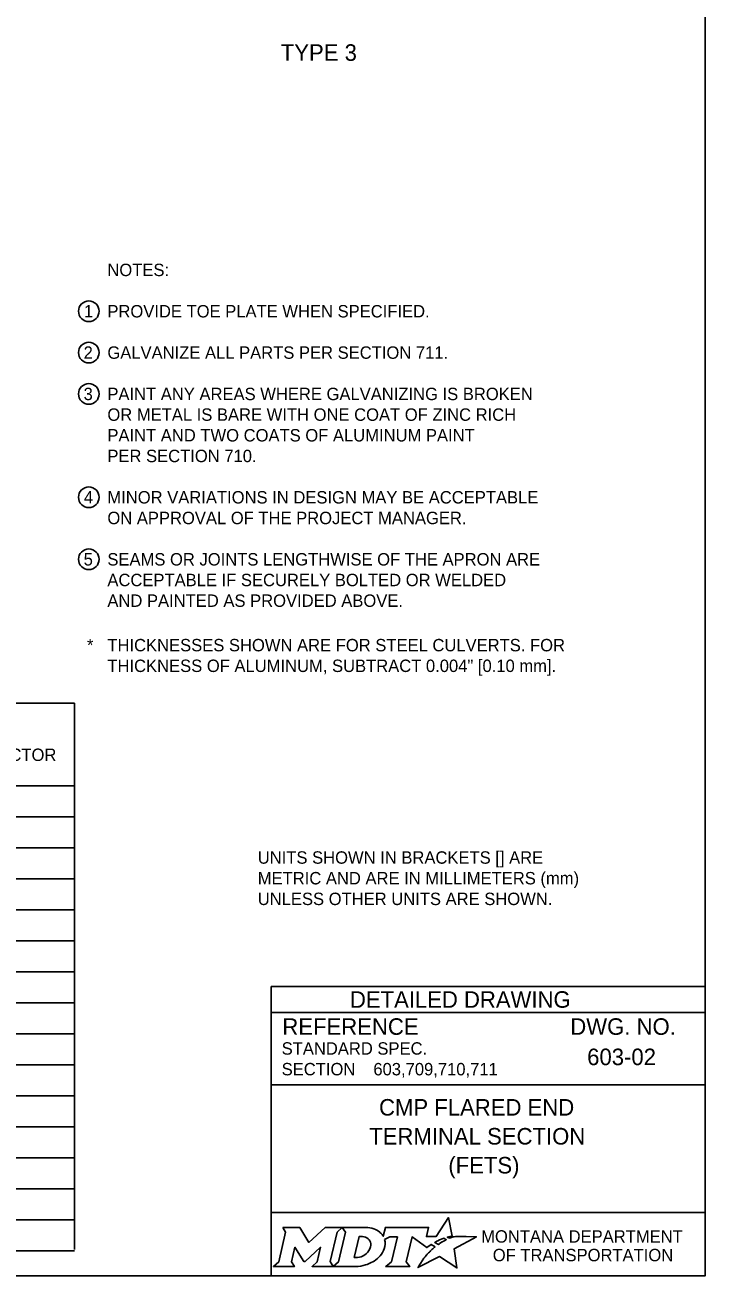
# Model space of a CAD drawing. Extents: x 49991.4 to 50021, y 49987.6 to 50011.4.
# Drawn here: x 50013.46 to 50016.75, y 49987.8 to 49993.85 of the extents above; entities that cross this region are included whole.
import ezdxf

# ---------------------------------------------------------------- set-up
doc = ezdxf.new("R2010")
doc.units = 0
for name, color, linetype in [('Default', 7, 'Continuous'), ('Level 1', 7, 'Continuous'), ('Level 2', 7, 'Continuous'), ('Level 5', 7, 'Continuous')]:
    doc.layers.add(name, color=color, linetype=linetype)

msp = doc.modelspace()

# ---------------------------------------------------------------- linework, layer by layer
at = {"layer": 'Default'}
for points in [[(50015.5126, 49987.9811), (50015.5023, 49987.9867), (50015.5139, 49987.9895), (50015.5255, 49987.9915), (50015.5081, 49988.0816), (50015.4486, 49987.9903), (50015.4013, 49987.9896), (50015.4116, 49988.0337), (50015.2024, 49988.0338), (50015.1923, 49987.9913), (50015.1865, 49987.9996)], [(50014.7056, 49988.0338), (50014.7197, 49988.0104), (50014.6862, 49987.8671), (50014.6605, 49987.8446), (50014.7621, 49987.8446), (50014.7486, 49987.8674), (50014.7648, 49987.9375), (50014.8085, 49987.8685), (50014.8138, 49987.8685), (50014.8889, 49987.938), (50014.8725, 49987.8669), (50014.8478, 49987.8449), (50014.9494, 49987.8449), (50014.9356, 49987.8682), (50014.9688, 49988.0106)], [(50014.9688, 49988.0106), (50014.9941, 49988.0338), (50014.9117, 49988.0338), (50014.8321, 49987.9608), (50014.7876, 49988.0335), (50014.7056, 49988.0338)], [(50015.1077, 49988.0338), (50014.9941, 49988.0338), (50015.0088, 49988.0109), (50014.9749, 49987.8671), (50014.9494, 49987.8449), (50015.06, 49987.8449)], [(50015.1317, 49987.9471), (50015.1305, 49987.939), (50015.1273, 49987.9297), (50015.1231, 49987.9215), (50015.1175, 49987.914), (50015.111, 49987.9071), (50015.1031, 49987.9008), (50015.0948, 49987.8961), (50015.0857, 49987.8922), (50015.0766, 49987.8899), (50015.0674, 49987.889), (50015.0515, 49987.889), (50015.0751, 49987.989), (50015.0911, 49987.989), (50015.0987, 49987.9884), (50015.1063, 49987.9865), (50015.1129, 49987.9835), (50015.119, 49987.9793), (50015.1238, 49987.9743), (50015.1275, 49987.9683), (50015.1302, 49987.9621), (50015.1318, 49987.9547), (50015.1318, 49987.9517), (50015.1317, 49987.9471)], [(50015.1991, 49987.9747), (50015.2237, 49987.9878), (50015.2606, 49987.9878), (50015.232, 49987.8673), (50015.2045, 49987.8446), (50015.3207, 49987.8446), (50015.3037, 49987.8675), (50015.3319, 49987.9877), (50015.4032, 49987.936), (50015.4243, 49987.9511), (50015.444, 49987.9402)], [(50015.3882, 49987.8843), (50015.3729, 49987.8599), (50015.3682, 49987.8524), (50015.3624, 49987.8438), (50015.3601, 49987.8395), (50015.4654, 49987.8926), (50015.5493, 49987.8375), (50015.5362, 49987.9302), (50015.6431, 49987.9886), (50015.5938, 49987.9894), (50015.5637, 49987.9898), (50015.5429, 49987.9901), (50015.5361, 49987.9886), (50015.5312, 49987.9874), (50015.5228, 49987.9851), (50015.5126, 49987.9811)], [(50015.4622, 49987.9535), (50015.4598, 49987.9518), (50015.4415, 49987.9614), (50015.4518, 49987.9671), (50015.4559, 49987.9693), (50015.4645, 49987.9733), (50015.4702, 49987.9759), (50015.4781, 49987.9789), (50015.4854, 49987.9816), (50015.4972, 49987.9742), (50015.4932, 49987.9721), (50015.4886, 49987.9696), (50015.4844, 49987.9674), (50015.4794, 49987.9645), (50015.4775, 49987.9634), (50015.4748, 49987.9618), (50015.4723, 49987.9604), (50015.47, 49987.9588), (50015.4674, 49987.957), (50015.4647, 49987.9552), (50015.4622, 49987.9535)], [(50015.1057, 49987.8522), (50015.1141, 49987.8548), (50015.1271, 49987.8602), (50015.1475, 49987.8712)], [(50015.4021, 49987.9004), (50015.4021, 49987.9004)]]:
    msp.add_lwpolyline(points, dxfattribs=at)
for centre, radius, start, end in [((50015.0868, 49987.9727), 0.1183, 300.91025, 339.13831), ((50015.1308, 49987.9554), 0.0709, 339.53292, 15.85821)]:
    msp.add_arc(centre, radius, start, end, dxfattribs=at)
for centre, major_axis, ratio, start_param, end_param in [((50015.1056, 49987.9864), (0.0834, -0.0037), 0.568097, 0.61298, 1.570796), ((50015.1612, 49987.9937), (0.0361, -0.0295), 0.469099, 1.225588, 1.570796), ((50015.4329, 49987.9305), (-0.0112, -0.0097), 0.021651, 3.157348, 6.283185), ((50015.3952, 49987.8923), (-0.00694, -0.00806), 0.008222, 0, 3.137361), ((50015.4119, 49987.9106), (-0.0098, -0.0102), 0.016458, 3.141593, 6.279097), ((50015.0603, 49987.9932), (0, 0.1484), 0.987302, 3.139398, 3.456847)]:
    msp.add_ellipse(centre, major_axis=major_axis, ratio=ratio, start_param=start_param, end_param=end_param, dxfattribs=at)
at = {"layer": 'Level 1'}
msp.add_lwpolyline([(49999.3835, 49998.9992), (50016.7501, 49998.9992), (50016.7501, 49987.7988), (49999.3835, 49987.7988)], close=True, dxfattribs=at)
at = {"layer": 'Level 2'}
for p, q in [((50007.3977, 49990.5701), (50013.6977, 49990.5701)), ((50013.6977, 49990.5701), (50013.6977, 49987.9267)), ((50007.3977, 49990.1701), (50013.6977, 49990.1701)), ((50007.3977, 49990.0201), (50013.6977, 49990.0201)), ((50007.3977, 49989.8701), (50013.6977, 49989.8701)), ((50007.3977, 49989.7201), (50013.6977, 49989.7201)), ((50007.3977, 49989.5701), (50013.6977, 49989.5701)), ((50007.3977, 49989.4201), (50013.6977, 49989.4201)), ((50007.3977, 49989.2701), (50013.6977, 49989.2701)), ((50007.3977, 49989.1201), (50013.6977, 49989.1201)), ((50007.3977, 49988.9701), (50013.6977, 49988.9701)), ((50007.3977, 49988.8201), (50013.6977, 49988.8201)), ((50007.3977, 49988.6701), (50013.6977, 49988.6701)), ((50007.3977, 49988.5201), (50013.6977, 49988.5201)), ((50007.3977, 49988.3701), (50013.6977, 49988.3701)), ((50007.3977, 49988.2201), (50013.6977, 49988.2201)), ((50007.3977, 49988.0701), (50013.6977, 49988.0701)), ((50007.3977, 49987.9201), (50013.6977, 49987.9201))]:
    msp.add_line(p, q, dxfattribs=at)
for centre in [(50013.7666, 49992.4657), (50013.7666, 49992.2657), (50013.7666, 49992.0657), (50013.7666, 49991.5657), (50013.7666, 49991.2657)]:
    msp.add_circle(centre, 0.05, dxfattribs=at)
at = {"layer": 'Level 5'}
for p, q in [((50016.7501, 49989.1988), (50014.6501, 49989.1988)), ((50014.6501, 49989.1988), (50014.6501, 49987.7988)), ((50016.7501, 49989.0738), (50014.6501, 49989.0738)), ((50016.3862, 49988.8587), (50016.3862, 49988.8587)), ((50015.1444, 49988.7993), (50015.1444, 49988.7993)), ((50016.7501, 49988.7238), (50014.6501, 49988.7238)), ((50015.7001, 49988.4747), (50015.7001, 49988.4747)), ((50016.7501, 49988.1057), (50014.6501, 49988.1057))]:
    msp.add_line(p, q, dxfattribs=at)

# ---------------------------------------------------------------- texts
at = {"layer": 'Default'}
for s, p in [('MONTANA DEPARTMENT', (50015.6663, 49987.96)), ('OF TRANSPORTATION', (50015.7225, 49987.87))]:
    msp.add_text(s, height=0.06, dxfattribs=at).set_placement(p)
at = {"layer": 'Level 2'}
for s, height, p in [('TYPE 3', 0.08, (50014.6961, 49993.6771)), ('NOTES:', 0.06, (50013.8566, 49992.6357)), ('1', 0.06, (50013.7431, 49992.4359)), ('PROVIDE TOE PLATE WHEN SPECIFIED.', 0.06, (50013.8566, 49992.4357)), ('2', 0.06, (50013.7415, 49992.2357)), ('GALVANIZE ALL PARTS PER SECTION 711.', 0.06, (50013.8566, 49992.2357)), ('3', 0.06, (50013.7414, 49992.0357)), ('PAINT ANY AREAS WHERE GALVANIZING IS BROKEN', 0.06, (50013.8566, 49992.0357)), ('OR METAL IS BARE WITH ONE COAT OF ZINC RICH', 0.06, (50013.8566, 49991.9357)), ('PAINT AND TWO COATS OF ALUMINUM PAINT', 0.06, (50013.8566, 49991.8357)), ('PER SECTION 710.', 0.06, (50013.8566, 49991.7357)), ('4', 0.06, (50013.7426, 49991.5357)), ('MINOR VARIATIONS IN DESIGN MAY BE ACCEPTABLE', 0.06, (50013.8566, 49991.5357)), ('ON APPROVAL OF THE PROJECT MANAGER.', 0.06, (50013.8566, 49991.4357)), ('5', 0.06, (50013.7417, 49991.2357)), ('SEAMS OR JOINTS LENGTHWISE OF THE APRON ARE', 0.06, (50013.8566, 49991.2357)), ('ACCEPTABLE IF SECURELY BOLTED OR WELDED', 0.06, (50013.8566, 49991.1357)), ('AND PAINTED AS PROVIDED ABOVE.', 0.06, (50013.8566, 49991.0357)), ('*', 0.06, (50013.758, 49990.8205)), ('THICKNESSES SHOWN ARE FOR STEEL CULVERTS. FOR', 0.06, (50013.8566, 49990.8205)), ('THICKNESS OF ALUMINUM, SUBTRACT 0.004" [0.10 mm].', 0.06, (50013.8566, 49990.7205)), ('CONNECTOR', 0.06, (50013.0926, 49990.2901)), ('UNITS SHOWN IN BRACKETS [] ARE ', 0.06, (50014.5847, 49989.7931)), ('METRIC AND ARE IN MILLIMETERS (mm) ', 0.06, (50014.5847, 49989.6931)), ('UNLESS OTHER UNITS ARE SHOWN.', 0.06, (50014.5847, 49989.5931)), ('603-02', 0.08, (50016.1796, 49988.8187)), ('603,709,710,711', 0.06, (50015.1444, 49988.7693)), ('CMP FLARED END', 0.08, (50015.1719, 49988.5747)), ('TERMINAL SECTION', 0.08, (50015.1243, 49988.4347)), ('(FETS)', 0.08, (50015.5073, 49988.2947))]:
    msp.add_text(s, height=height, dxfattribs=at).set_placement(p)
at = {"layer": 'Level 5'}
for s, height, p in [('DETAILED DRAWING', 0.0799, (50015.0311, 49989.0963)), ('REFERENCE', 0.08, (50014.7037, 49988.9654)), ('DWG. NO.', 0.08, (50016.0979, 49988.9654)), ('STANDARD SPEC.', 0.06, (50014.7004, 49988.8694)), ('SECTION', 0.06, (50014.7004, 49988.7694))]:
    msp.add_text(s, height=height, dxfattribs=at).set_placement(p)

doc.saveas('drawing.dxf')
